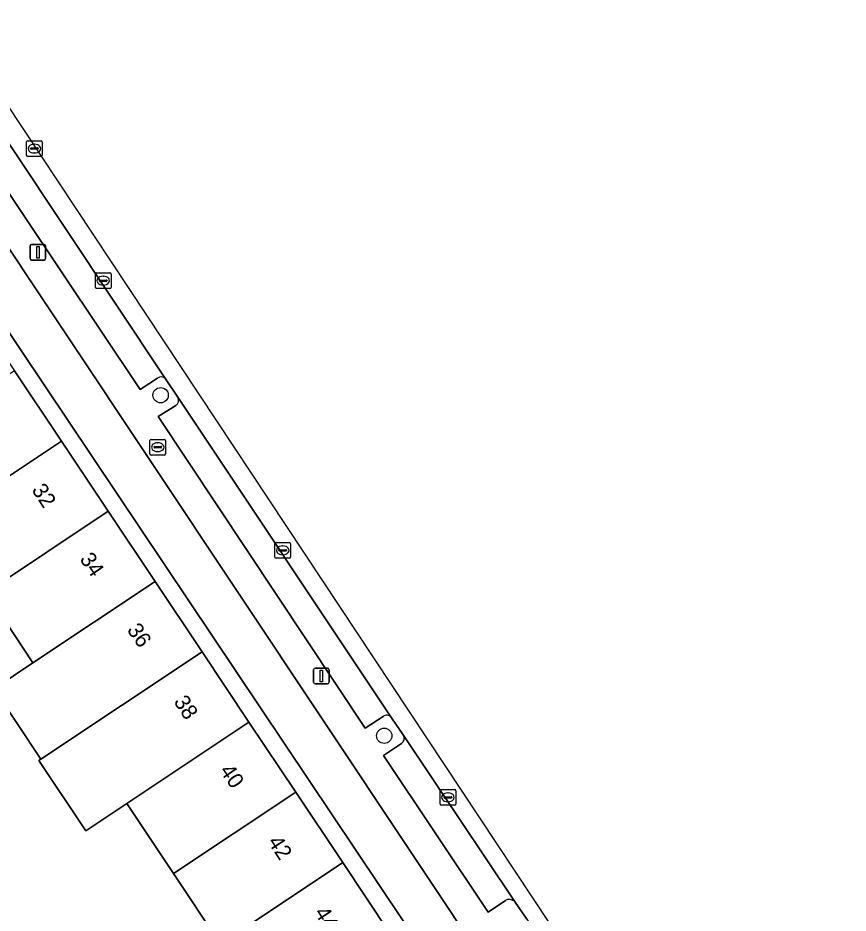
# Model space of a CAD drawing. Extents: x 158352 to 159489, y 383828 to 384603.
# Drawn here: x 158924.3 to 158977.3, y 384354.9 to 384412.1 of the extents above; entities that cross this region are included whole.
import ezdxf

# ---------------------------------------------------------------- set-up
doc = ezdxf.new("R2010")
doc.units = 0
for name, color, linetype in [('IMGEO_Boom', 7, 'Continuous'), ('IMGEO_Brandkraan', 7, 'Continuous'), ('IMGEO_Erf', 7, 'Continuous'), ('IMGEO_Kolk', 7, 'Continuous'), ('IMGEO_Lichtmast', 7, 'Continuous'), ('IMGEO_Pand', 7, 'Continuous'), ('IMGEO_Pand_nummerreeks', 7, 'Continuous'), ('IMGEO_Parkeervlak_open', 7, 'Continuous'), ('IMGEO_Rijbaan_lokaal_gesloten', 7, 'Continuous'), ('IMGEO_Rioolput', 7, 'Continuous'), ('IMGEO_Voetpad_open', 7, 'Continuous')]:
    doc.layers.add(name, color=color, linetype=linetype)

msp = doc.modelspace()

# ---------------------------------------------------------------- linework, layer by layer
at = {"layer": 'IMGEO_Boom'}
for centre in [(158933.366, 384388.02), (158947.643, 384366.263)]:
    msp.add_circle(centre, 0.489, dxfattribs=at)
at = {"layer": 'IMGEO_Brandkraan'}
for p, q in [((158932.682, 384384.272), (158932.682, 384385.124)), ((158932.757, 384385.198), (158933.609, 384385.198)), ((158932.941, 384384.692), (158932.941, 384384.704)), ((158933.379, 384384.655), (158932.981, 384384.655)), ((158932.984, 384384.741), (158933.382, 384384.741)), ((158933.17, 384384.978), (158933.195, 384384.978)), ((158933.425, 384384.704), (158933.425, 384384.692)), ((158933.683, 384385.124), (158933.683, 384384.272)), ((158933.609, 384384.198), (158932.757, 384384.198)), ((158933.193, 384384.418), (158933.168, 384384.418))]:
    msp.add_line(p, q, dxfattribs=at)
for points in [[(158932.682, 384384.272), (158932.682, 384385.124)], [(158932.757, 384385.198), (158933.609, 384385.198)], [(158933.683, 384385.124), (158933.683, 384384.272)], [(158933.609, 384384.198), (158932.757, 384384.198)]]:
    msp.add_lwpolyline(points, dxfattribs=at)
for centre, radius, start, end in [((158932.759, 384385.122), 0.0765, 91.552, 178.448), ((158932.759, 384385.122), 0.0765, 91.552, 178.448), ((158932.981, 384384.701), 0.0403, 85.8775, 175.7526), ((158932.978, 384384.691), 0.0366, 178.938, 274.7102), ((158933.382, 384384.698), 0.043, 264.8664, 352.4533), ((158933.386, 384384.703), 0.0386, 1.7309, 96.639), ((158933.607, 384385.122), 0.0765, 1.552, 88.448), ((158933.607, 384385.122), 0.0765, 1.552, 88.448), ((158932.759, 384384.274), 0.0765, 181.552, 268.448), ((158932.759, 384384.274), 0.0765, 181.552, 268.448), ((158933.607, 384384.274), 0.0765, 271.552, 358.448), ((158933.607, 384384.274), 0.0765, 271.552, 358.448)]:
    msp.add_arc(centre, radius, start, end, dxfattribs=at)
for centre, major_axis, ratio, start_param, end_param in [((158933.169, 384384.698), (-0.387, 0.002), 0.722429, 4.712389, 7.853982), ((158933.194, 384384.698), (-0.39, 0.002), 0.717154, 1.570796, 4.712389)]:
    msp.add_ellipse(centre, major_axis=major_axis, ratio=ratio, start_param=start_param, end_param=end_param, dxfattribs=at)
at = {"layer": 'IMGEO_Erf'}
msp.add_lwpolyline([(158899.598, 384433.573), (158885.345, 384454.99), (158882.708, 384453.235), (158896.943, 384431.973), (158958.047, 384340.708), (158960.345, 384342.297)], close=True, dxfattribs=at)
for points in [[(158906.071, 384416.517), (158909.059, 384412.037), (158912.058, 384407.541), (158915.047, 384403.061), (158918.046, 384398.564), (158921.035, 384394.084), (158924.033, 384389.586), (158927.032, 384385.093), (158930.022, 384380.611), (158933.021, 384376.115), (158936.009, 384371.634), (158939.008, 384367.138), (158941.997, 384362.657), (158944.995, 384358.163), (158947.985, 384353.68), (158950.984, 384349.185), (158953.98, 384344.687), (158957.083, 384340.042), (158958.057, 384340.693), (158958.047, 384340.708), (158896.943, 384431.973)], [(158937.182, 384352.958), (158934.185, 384357.453), (158931.198, 384361.934), (158928.579, 384360.189), (158925.581, 384364.685), (158925.707, 384364.769), (158922.719, 384369.251), (158925.212, 384370.913), (158922.215, 384375.409)]]:
    msp.add_lwpolyline(points, dxfattribs=at)
at = {"layer": 'IMGEO_Kolk'}
for p, q in [((158929.198, 384394.909), (158929.198, 384395.761)), ((158929.273, 384395.835), (158930.125, 384395.835)), ((158929.686, 384395.615), (158929.711, 384395.615)), ((158930.199, 384395.761), (158930.199, 384394.909)), ((158929.457, 384395.329), (158929.457, 384395.341)), ((158929.895, 384395.292), (158929.497, 384395.292)), ((158929.5, 384395.378), (158929.898, 384395.378)), ((158929.709, 384395.055), (158929.684, 384395.055)), ((158929.941, 384395.341), (158929.941, 384395.329)), ((158930.125, 384394.835), (158929.273, 384394.835)), ((158940.665, 384377.68), (158940.665, 384378.532)), ((158940.74, 384378.606), (158941.592, 384378.606)), ((158941.153, 384378.386), (158941.178, 384378.386)), ((158941.666, 384378.532), (158941.666, 384377.68)), ((158940.924, 384378.1), (158940.924, 384378.112)), ((158941.362, 384378.063), (158940.964, 384378.063)), ((158940.967, 384378.149), (158941.365, 384378.149)), ((158941.176, 384377.826), (158941.151, 384377.826)), ((158941.408, 384378.112), (158941.408, 384378.1)), ((158941.592, 384377.606), (158940.74, 384377.606)), ((158951.209, 384361.901), (158951.209, 384362.753)), ((158951.284, 384362.827), (158952.136, 384362.827)), ((158951.511, 384362.37), (158951.909, 384362.37)), ((158951.697, 384362.607), (158951.722, 384362.607)), ((158952.21, 384362.753), (158952.21, 384361.901)), ((158952.136, 384361.827), (158951.284, 384361.827)), ((158951.468, 384362.321), (158951.468, 384362.333)), ((158951.906, 384362.284), (158951.508, 384362.284)), ((158951.72, 384362.047), (158951.695, 384362.047)), ((158951.952, 384362.333), (158951.952, 384362.321))]:
    msp.add_line(p, q, dxfattribs=at)
for points in [[(158929.198, 384394.909), (158929.198, 384395.761)], [(158929.273, 384395.835), (158930.125, 384395.835)], [(158930.199, 384395.761), (158930.199, 384394.909)], [(158930.125, 384394.835), (158929.273, 384394.835)], [(158940.665, 384377.68), (158940.665, 384378.532)], [(158940.74, 384378.606), (158941.592, 384378.606)], [(158941.666, 384378.532), (158941.666, 384377.68)], [(158941.592, 384377.606), (158940.74, 384377.606)], [(158951.209, 384361.901), (158951.209, 384362.753)], [(158951.284, 384362.827), (158952.136, 384362.827)], [(158952.21, 384362.753), (158952.21, 384361.901)], [(158952.136, 384361.827), (158951.284, 384361.827)]]:
    msp.add_lwpolyline(points, dxfattribs=at)
for centre, radius, start, end in [((158929.275, 384395.759), 0.0765, 91.552, 178.448), ((158929.275, 384395.759), 0.0765, 91.552, 178.448), ((158930.123, 384395.759), 0.0765, 1.552, 88.448), ((158930.123, 384395.759), 0.0765, 1.552, 88.448), ((158929.497, 384395.338), 0.0403, 85.8775, 175.7526), ((158929.494, 384395.328), 0.0366, 178.938, 274.7102), ((158929.898, 384395.335), 0.043, 264.8664, 352.4533), ((158929.902, 384395.34), 0.0386, 1.7309, 96.639), ((158929.275, 384394.911), 0.0765, 181.552, 268.448), ((158929.275, 384394.911), 0.0765, 181.552, 268.448), ((158930.123, 384394.911), 0.0765, 271.552, 358.448), ((158930.123, 384394.911), 0.0765, 271.552, 358.448), ((158940.742, 384378.53), 0.0765, 91.552, 178.448), ((158940.742, 384378.53), 0.0765, 91.552, 178.448), ((158941.59, 384378.53), 0.0765, 1.552, 88.448), ((158941.59, 384378.53), 0.0765, 1.552, 88.448), ((158940.964, 384378.109), 0.0403, 85.8775, 175.7526), ((158940.961, 384378.099), 0.0366, 178.938, 274.7102), ((158941.365, 384378.106), 0.043, 264.8664, 352.4533), ((158941.369, 384378.111), 0.0386, 1.7309, 96.639), ((158940.742, 384377.682), 0.0765, 181.552, 268.448), ((158940.742, 384377.682), 0.0765, 181.552, 268.448), ((158941.59, 384377.682), 0.0765, 271.552, 358.448), ((158941.59, 384377.682), 0.0765, 271.552, 358.448), ((158951.286, 384362.751), 0.0765, 91.552, 178.448), ((158951.286, 384362.751), 0.0765, 91.552, 178.448), ((158951.508, 384362.33), 0.0403, 85.8775, 175.7526), ((158951.913, 384362.332), 0.0386, 1.7309, 96.639), ((158952.134, 384362.751), 0.0765, 1.552, 88.448), ((158952.134, 384362.751), 0.0765, 1.552, 88.448), ((158951.286, 384361.903), 0.0765, 181.552, 268.448), ((158951.286, 384361.903), 0.0765, 181.552, 268.448), ((158951.505, 384362.32), 0.0366, 178.938, 274.7102), ((158951.909, 384362.327), 0.043, 264.8664, 352.4533), ((158952.134, 384361.903), 0.0765, 271.552, 358.448), ((158952.134, 384361.903), 0.0765, 271.552, 358.448)]:
    msp.add_arc(centre, radius, start, end, dxfattribs=at)
for centre, major_axis, ratio, start_param, end_param in [((158929.685, 384395.335), (-0.387, 0.002), 0.722429, 4.712389, 7.853982), ((158929.71, 384395.335), (-0.39, 0.002), 0.717154, 1.570796, 4.712389), ((158941.152, 384378.106), (-0.387, 0.002), 0.722429, 4.712389, 7.853982), ((158941.177, 384378.106), (-0.39, 0.002), 0.717154, 1.570796, 4.712389), ((158951.696, 384362.327), (-0.387, 0.002), 0.722429, 4.712389, 7.853982), ((158951.721, 384362.327), (-0.39, 0.002), 0.717154, 1.570796, 4.712389)]:
    msp.add_ellipse(centre, major_axis=major_axis, ratio=ratio, start_param=start_param, end_param=end_param, dxfattribs=at)
at = {"layer": 'IMGEO_Lichtmast'}
for p, q in [((158925.03, 384396.754), (158925.03, 384397.554)), ((158925.03, 384397.554), (158925.03, 384396.754)), ((158925.13, 384397.654), (158925.92, 384397.654)), ((158925.92, 384397.654), (158925.13, 384397.654)), ((158926.02, 384397.554), (158926.02, 384396.754)), ((158926.02, 384396.754), (158926.02, 384397.554)), ((158925.92, 384396.654), (158925.13, 384396.654)), ((158925.13, 384396.654), (158925.92, 384396.654)), ((158943.134, 384369.678), (158943.134, 384370.478)), ((158943.134, 384370.478), (158943.134, 384369.678)), ((158943.234, 384370.578), (158944.024, 384370.578)), ((158944.024, 384370.578), (158943.234, 384370.578)), ((158944.124, 384370.478), (158944.124, 384369.678)), ((158944.124, 384369.678), (158944.124, 384370.478)), ((158944.024, 384369.578), (158943.234, 384369.578)), ((158943.234, 384369.578), (158944.024, 384369.578))]:
    msp.add_line(p, q, dxfattribs=at)
for points in [[(158925.45, 384397.529), (158925.6, 384397.529), (158925.6, 384396.779), (158925.45, 384396.779), (158925.45, 384397.529)], [(158943.554, 384370.453), (158943.704, 384370.453), (158943.704, 384369.703), (158943.554, 384369.703), (158943.554, 384370.453)]]:
    msp.add_lwpolyline(points, dxfattribs=at)
for centre, start, end in [((158925.13, 384397.554), 90, 180), ((158925.13, 384397.554), 90, 180), ((158925.92, 384397.554), 0, 90), ((158925.92, 384397.554), 360, 90), ((158925.13, 384396.754), 180, 270), ((158925.13, 384396.754), 180, 270), ((158925.92, 384396.754), 270, 0), ((158925.92, 384396.754), 270, 0), ((158943.234, 384370.478), 90, 180), ((158943.234, 384370.478), 90, 180), ((158944.024, 384370.478), 0, 90), ((158944.024, 384370.478), 360, 90), ((158943.234, 384369.678), 180, 270), ((158943.234, 384369.678), 180, 270), ((158944.024, 384369.678), 270, 0), ((158944.024, 384369.678), 270, 0)]:
    msp.add_arc(centre, 0.1, start, end, dxfattribs=at)
at = {"layer": 'IMGEO_Pand'}
for points in [[(158916.226, 384384.386), (158919.225, 384379.892), (158927.032, 384385.093), (158924.033, 384389.586)], [(158927.032, 384385.093), (158919.225, 384379.892), (158922.215, 384375.409), (158930.022, 384380.611)], [(158930.022, 384380.611), (158922.215, 384375.409), (158925.212, 384370.913), (158933.021, 384376.115)], [(158936.009, 384371.634), (158933.021, 384376.115), (158925.212, 384370.913), (158922.719, 384369.251), (158925.707, 384364.769)], [(158939.008, 384367.138), (158936.009, 384371.634), (158925.707, 384364.769), (158925.581, 384364.685), (158928.579, 384360.189), (158931.198, 384361.934)], [(158941.997, 384362.657), (158939.008, 384367.138), (158931.198, 384361.934), (158934.185, 384357.453)], [(158937.182, 384352.958), (158944.995, 384358.163), (158941.997, 384362.657), (158934.185, 384357.453)], [(158937.182, 384352.958), (158940.171, 384348.474), (158947.985, 384353.68), (158944.995, 384358.163)]]:
    msp.add_lwpolyline(points, close=True, dxfattribs=at)
at = {"layer": 'IMGEO_Parkeervlak_open'}
for points in [[(158933.684, 384389.073), (158920.763, 384408.459)], [(158920.652, 384407.923), (158919.498, 384407.15), (158932.053, 384388.385), (158933.158, 384389.116)], [(158948.108, 384367.417), (158934.462, 384387.903)], [(158934.332, 384387.359), (158933.215, 384386.663), (158946.419, 384366.755), (158947.569, 384367.491)], [(158948.742, 384365.766), (158947.59, 384364.999), (158954.28, 384354.983), (158955.379, 384355.738)], [(158955.957, 384355.688), (158948.862, 384366.323)]]:
    msp.add_lwpolyline(points, dxfattribs=at)
for centre, radius, start, end in [((158933.395, 384388.771), 0.418, 46.1733, 124.4797), ((158934.123, 384387.697), 0.397, 301.7806, 31.3395), ((158947.805, 384367.211), 0.366, 34.1776, 130.1877), ((158948.522, 384366.105), 0.404, 302.9879, 32.6962), ((158955.632, 384355.3), 0.506, 50.0957, 120.0161)]:
    msp.add_arc(centre, radius, start, end, dxfattribs=at)
at = {"layer": 'IMGEO_Rijbaan_lokaal_gesloten'}
for points in [[(158875.263, 384479.53), (158874.302, 384478.867), (158874.82, 384477.468), (158884.4, 384463.1), (158888.28, 384457.252), (158898.259, 384442.243), (158899.028, 384441.124), (158902.775, 384435.489), (158906.139, 384430.429), (158906.908, 384429.304), (158920.007, 384409.58), (158920.763, 384408.459), (158933.684, 384389.073), (158934.462, 384387.903), (158948.108, 384367.417), (158948.862, 384366.323), (158955.957, 384355.688), (158956.746, 384354.542), (158963.568, 384344.252), (158966.627, 384339.706), (158967.515, 384338.34), (158974.141, 384328.364)], [(158974.618, 384328.235), (158976.716, 384325.103), (158977.265, 384325.504), (158977.265, 384325.504), (158875.263, 384479.53)]]:
    msp.add_lwpolyline(points, dxfattribs=at)
at = {"layer": 'IMGEO_Rioolput'}
for p, q in [((158924.807, 384403.348), (158924.807, 384404.2)), ((158924.882, 384404.274), (158925.734, 384404.274)), ((158925.808, 384404.2), (158925.808, 384403.348)), ((158925.066, 384403.768), (158925.066, 384403.78)), ((158925.504, 384403.731), (158925.106, 384403.731)), ((158925.109, 384403.817), (158925.507, 384403.817)), ((158925.295, 384404.054), (158925.32, 384404.054)), ((158925.55, 384403.78), (158925.55, 384403.768)), ((158925.734, 384403.274), (158924.882, 384403.274)), ((158925.318, 384403.494), (158925.293, 384403.494))]:
    msp.add_line(p, q, dxfattribs=at)
for points in [[(158924.807, 384403.348), (158924.807, 384404.2)], [(158924.882, 384404.274), (158925.734, 384404.274)], [(158925.808, 384404.2), (158925.808, 384403.348)], [(158925.734, 384403.274), (158924.882, 384403.274)]]:
    msp.add_lwpolyline(points, dxfattribs=at)
for centre, radius, start, end in [((158924.884, 384404.198), 0.0765, 91.552, 178.448), ((158924.884, 384404.198), 0.0765, 91.552, 178.448), ((158925.732, 384404.198), 0.0765, 1.552, 88.448), ((158925.732, 384404.198), 0.0765, 1.552, 88.448), ((158925.106, 384403.777), 0.0403, 85.8775, 175.7526), ((158925.103, 384403.767), 0.0366, 178.938, 274.7102), ((158925.507, 384403.774), 0.043, 264.8664, 352.4533), ((158925.511, 384403.779), 0.0386, 1.7309, 96.639), ((158924.884, 384403.35), 0.0765, 181.552, 268.448), ((158924.884, 384403.35), 0.0765, 181.552, 268.448), ((158925.732, 384403.35), 0.0765, 271.552, 358.448), ((158925.732, 384403.35), 0.0765, 271.552, 358.448)]:
    msp.add_arc(centre, radius, start, end, dxfattribs=at)
for centre, major_axis, ratio, start_param, end_param in [((158925.294, 384403.774), (-0.387, 0.002), 0.722429, 4.712389, 7.853982), ((158925.319, 384403.774), (-0.39, 0.002), 0.717154, 1.570796, 4.712389)]:
    msp.add_ellipse(centre, major_axis=major_axis, ratio=ratio, start_param=start_param, end_param=end_param, dxfattribs=at)
at = {"layer": 'IMGEO_Voetpad_open'}
for points in [[(158883.84, 384463.169), (158882.723, 384462.395), (158872.711, 384477.381), (158871.439, 384475.884), (158884.184, 384456.734), (158885.345, 384454.99), (158899.598, 384433.573), (158960.345, 384342.297), (158973.377, 384322.58), (158974.997, 384323.628), (158974.847, 384323.853), (158976.716, 384325.103), (158974.618, 384328.235)], [(158933.158, 384389.116), (158932.053, 384388.385), (158919.498, 384407.15), (158920.652, 384407.923)], [(158934.462, 384387.903), (158933.684, 384389.073)], [(158947.569, 384367.491), (158946.419, 384366.755), (158933.215, 384386.663), (158934.332, 384387.359)], [(158948.862, 384366.323), (158948.108, 384367.417)], [(158955.379, 384355.738), (158954.28, 384354.983), (158947.59, 384364.999), (158948.742, 384365.766)], [(158956.746, 384354.542), (158955.957, 384355.688)]]:
    msp.add_lwpolyline(points, dxfattribs=at)
for centre, radius, start, end in [((158933.395, 384388.771), 0.418, 46.1733, 124.4797), ((158934.123, 384387.697), 0.397, 301.7806, 31.3395), ((158947.805, 384367.211), 0.366, 34.1776, 130.1877), ((158948.522, 384366.105), 0.404, 302.9879, 32.6962), ((158955.632, 384355.3), 0.506, 50.0957, 120.0161)]:
    msp.add_arc(centre, radius, start, end, dxfattribs=at)

# ---------------------------------------------------------------- texts
at = {"layer": 'IMGEO_Pand_nummerreeks'}
for s, rotation, p in [('32', 303.2386, (158925.098, 384381.97)), ('34', 304.2783, (158928.16, 384377.549)), ('36', 304.8528, (158931.18, 384373.023)), ('38', 303.1053, (158934.168, 384368.442)), ('40', 304.8159, (158937.095, 384364.025)), ('42', 303.253, (158940.174, 384359.485)), ('44', 303.1213, (158943.146, 384354.957))]:
    msp.add_text(s, height=1, rotation=rotation, dxfattribs=at).set_placement(p)

doc.saveas('drawing.dxf')
